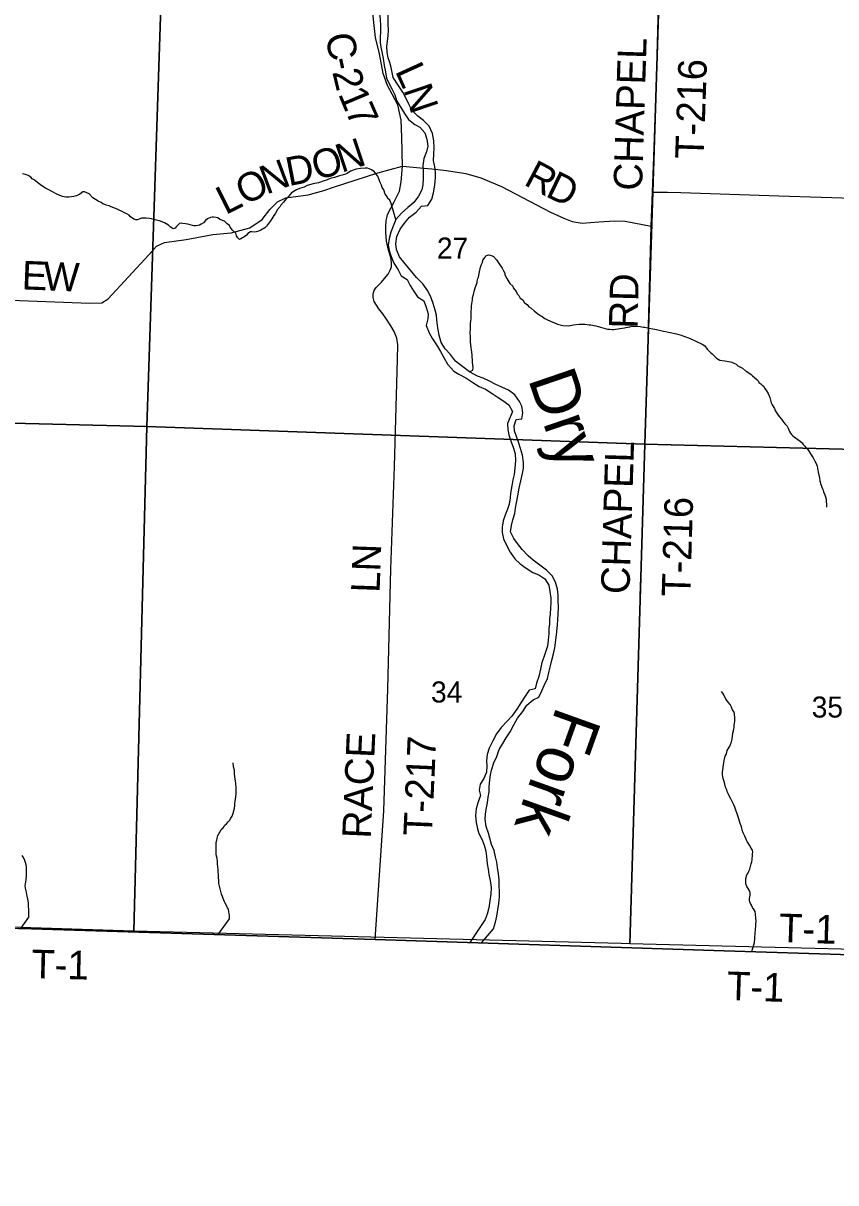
# Model space of a CAD drawing. Extents: x 1310247 to 1552180, y 377264 to 706493.
# Drawn here: x 1328257 to 1336785, y 480623 to 492789 of the extents above; entities that cross this region are included whole.
import ezdxf

# ---------------------------------------------------------------- set-up
doc = ezdxf.new("R2010")
doc.units = 0
for name, color, linetype in [('GM_X_Adjacent_County', 7, 'Continuous'), ('GM_X_County', 7, 'Continuous'), ('GM_X_County_Road', 7, 'Continuous'), ('GM_X_County_Road_Text', 7, 'Continuous'), ('GM_X_Minor_River', 7, 'Continuous'), ('GM_X_Minor_River_Text', 7, 'Continuous'), ('GM_X_Section', 7, 'Continuous'), ('GM_X_Section_Text', 7, 'Continuous'), ('GM_X_Township', 7, 'Continuous'), ('GM_X_Township_Road', 7, 'Continuous'), ('GM_X_Township_Road_Text', 7, 'Continuous'), ('GM_X_Township_ROW', 7, 'Continuous')]:
    doc.layers.add(name, color=color, linetype=linetype)

msp = doc.modelspace()

# ---------------------------------------------------------------- linework, layer by layer
at = {"layer": 'GM_X_Adjacent_County'}
msp.add_lwpolyline([(1311930, 473340), (1312230, 481623), (1312308, 483784), (1318929, 483579), (1321046, 483514), (1321136, 483511), (1321869, 483488), (1322123, 483480), (1323707, 483431), (1325989, 483347), (1327303, 483322), (1327412, 483318), (1328130, 483294), (1328206, 483291), (1328343, 483287), (1331950, 483175), (1335615, 483058), (1337392, 483001)], dxfattribs=at)
at = {"layer": 'GM_X_County'}
msp.add_lwpolyline([(1337392, 483001), (1335615, 483058), (1331950, 483175), (1328343, 483287), (1328206, 483291)], dxfattribs=at)
at = {"layer": 'GM_X_County_Road'}
for points in [[(1332238, 491289), (1332231, 491593), (1332223, 491770), (1332190, 491933), (1332130, 492044), (1332082, 492136), (1332035, 492261), (1331996, 492468), (1331955, 492638), (1331915, 492990), (1331892, 493143), (1331876, 493464), (1331840, 493608), (1331766, 493746), (1331651, 493921), (1331448, 494140), (1331228, 494295), (1330896, 494460), (1330638, 494558), (1330379, 494645), (1330272, 494712), (1330218, 494757), (1330196, 494814), (1330194, 494825)], [(1327573, 489903), (1328958, 489851), (1329081, 489855), (1329149, 489897), (1329574, 490360), (1329655, 490448), (1329739, 490487), (1329966, 490518), (1330247, 490572), (1330440, 490588), (1330634, 490643), (1330764, 490728), (1330847, 490836), (1330926, 490915), (1331013, 490955), (1331247, 490988), (1331412, 491034), (1331515, 491067), (1331979, 491219), (1332238, 491289)], [(1332238, 491289), (1332349, 491278), (1332424, 491271), (1332546, 491261), (1332699, 491245), (1332903, 491213), (1333059, 491167), (1333275, 491077), (1333792, 490808), (1333930, 490743), (1334020, 490708), (1334124, 490692), (1334297, 490704), (1334467, 490715), (1334574, 490712), (1334848, 490661), (1334863, 491017), (1335018, 491015)], [(1335018, 491015), (1335159, 491013), (1336186, 490979), (1337074, 490951), (1337926, 490924), (1338970, 490886), (1339596, 490862), (1340611, 490828), (1341219, 490803), (1341888, 490779), (1342113, 490773)]]:
    msp.add_lwpolyline(points, dxfattribs=at)
at = {"layer": 'GM_X_Minor_River'}
msp.add_line((1332943, 483144), (1333068, 483140), dxfattribs=at)
for points in [[(1331933, 493545), (1331942, 493468), (1331950, 493390), (1331950, 493338), (1331960, 493257), (1331970, 493198), (1331978, 493134), (1331983, 493055), (1331986, 493005), (1331990, 492954), (1331998, 492888), (1332004, 492827), (1332008, 492765), (1332006, 492697), (1332002, 492641), (1332004, 492586), (1332011, 492536), (1332025, 492471), (1332035, 492419), (1332047, 492346), (1332060, 492277), (1332070, 492210), (1332127, 492101)], [(1332140, 492219), (1332118, 492325), (1332104, 492376), (1332087, 492427), (1332077, 492482), (1332075, 492548), (1332079, 492600), (1332089, 492660), (1332091, 492714), (1332089, 492779), (1332086, 492831), (1332088, 492897)], [(1333790, 486048), (1333806, 486106), (1333824, 486174), (1333838, 486236), (1333843, 486288), (1333859, 486404), (1333865, 486476), (1333869, 486534), (1333872, 486590), (1333876, 486664), (1333872, 486735), (1333870, 486785), (1333864, 486850), (1333844, 486924), (1333808, 486992), (1333749, 487050), (1333678, 487104), (1333610, 487156), (1333555, 487202), (1333493, 487268), (1333444, 487330), (1333406, 487381), (1333372, 487454), (1333381, 487518), (1333395, 487578), (1333415, 487644), (1333425, 487700), (1333434, 487758), (1333447, 487832), (1333463, 487912), (1333481, 487987), (1333496, 488063), (1333509, 488121), (1333509, 488181), (1333497, 488258), (1333477, 488327), (1333459, 488382), (1333436, 488441), (1333414, 488513), (1333408, 488564), (1333430, 488632), (1333490, 488638), (1333502, 488702), (1333490, 488770), (1333467, 488821), (1333415, 488889), (1333350, 488939), (1333279, 488971), (1333216, 488999), (1333151, 489035), (1333083, 489065), (1333024, 489085), (1332941, 489130), (1332872, 489182), (1332795, 489243), (1332741, 489314), (1332687, 489372), (1332643, 489440), (1332621, 489517), (1332607, 489593), (1332599, 489676), (1332593, 489726), (1332580, 489777), (1332560, 489848), (1332538, 489909), (1332504, 489980), (1332450, 490056), (1332386, 490120), (1332320, 490198), (1332264, 490266), (1332207, 490338), (1332174, 490415), (1332167, 490474), (1332178, 490552), (1332214, 490629), (1332258, 490690), (1332312, 490753), (1332380, 490807), (1332438, 490869), (1332504, 490878), (1332544, 490943), (1332564, 491010), (1332574, 491068), (1332579, 491120), (1332585, 491176), (1332583, 491229), (1332578, 491281), (1332564, 491350), (1332566, 491414), (1332570, 491484), (1332566, 491554), (1332552, 491633), (1332516, 491708), (1332458, 491768), (1332397, 491814), (1332337, 491878), (1332301, 491946), (1332274, 492005), (1332242, 492066), (1332194, 492140), (1332140, 492219)], [(1332127, 492101), (1332157, 492038), (1332175, 491978), (1332260, 491843), (1332302, 491779), (1332366, 491727), (1332420, 491697), (1332472, 491637), (1332492, 491571), (1332502, 491500), (1332490, 491438), (1332460, 491369), (1332450, 491295), (1332454, 491232), (1332456, 491160), (1332452, 491094), (1332439, 491042), (1332405, 490973), (1332358, 490906), (1332295, 490854), (1332229, 490797), (1332167, 490731), (1332139, 490661), (1332115, 490596), (1332097, 490530), (1332089, 490460), (1332103, 490391), (1332119, 490341), (1332147, 490272), (1332191, 490202), (1332224, 490139), (1332285, 490099), (1332319, 490038), (1332352, 489980), (1332394, 489919), (1332463, 489875), (1332487, 489808), (1332507, 489739), (1332505, 489687), (1332487, 489619), (1332517, 489542), (1332553, 489477), (1332596, 489413), (1332638, 489344), (1332672, 489280), (1332710, 489211), (1332778, 489137), (1332830, 489107), (1332903, 489069), (1332976, 489020), (1333041, 488978), (1333110, 488950), (1333179, 488904), (1333230, 488868), (1333291, 488830), (1333354, 488784), (1333392, 488715), (1333368, 488655), (1333338, 488590), (1333342, 488524), (1333355, 488471), (1333379, 488396), (1333401, 488329), (1333419, 488270), (1333425, 488200), (1333417, 488120), (1333411, 488054), (1333397, 487998), (1333385, 487934), (1333371, 487860), (1333366, 487808), (1333356, 487744), (1333340, 487690), (1333319, 487639), (1333295, 487567), (1333285, 487503), (1333285, 487445), (1333299, 487378), (1333331, 487307), (1333369, 487238), (1333417, 487170), (1333474, 487118), (1333535, 487072), (1333604, 487026), (1333669, 487000), (1333732, 486960), (1333773, 486892), (1333783, 486826), (1333793, 486757), (1333795, 486705), (1333792, 486655), (1333786, 486589), (1333782, 486539), (1333781, 486488), (1333775, 486438), (1333772, 486386), (1333768, 486316), (1333758, 486254), (1333743, 486202), (1333721, 486137), (1333701, 486081)], [(1332167, 490731), (1332119, 490898), (1332104, 490931), (1332084, 490951), (1332081, 490965), (1332057, 490996), (1332041, 491039), (1332023, 491065), (1332016, 491088), (1332003, 491116), (1331993, 491144), (1331978, 491183), (1331963, 491206), (1331940, 491234), (1331904, 491255), (1331869, 491267), (1331847, 491269), (1331796, 491265), (1331750, 491258), (1331693, 491238), (1331656, 491213), (1331638, 491205), (1331606, 491194), (1331575, 491187), (1331545, 491178), (1331523, 491171), (1331478, 491158), (1331441, 491143), (1331415, 491134), (1331356, 491115), (1331300, 491105), (1331239, 491087), (1331205, 491070), (1331158, 491055), (1331127, 491040), (1331072, 491008), (1331037, 490967), (1331020, 490949), (1330989, 490910), (1330960, 490881), (1330954, 490867), (1330925, 490835), (1330901, 490788), (1330889, 490770), (1330868, 490735), (1330851, 490715), (1330841, 490700), (1330832, 490686), (1330809, 490660), (1330793, 490641), (1330750, 490616), (1330726, 490607), (1330703, 490601), (1330681, 490598), (1330655, 490601), (1330641, 490599), (1330616, 490582), (1330602, 490566), (1330573, 490545), (1330559, 490538), (1330541, 490526), (1330526, 490520), (1330509, 490537), (1330495, 490558), (1330490, 490586), (1330453, 490619), (1330430, 490650), (1330422, 490666), (1330397, 490685), (1330385, 490699), (1330369, 490712), (1330322, 490731), (1330300, 490746), (1330284, 490750), (1330256, 490753), (1330242, 490754), (1330222, 490750), (1330193, 490737), (1330171, 490718), (1330148, 490696), (1330126, 490679), (1330107, 490669), (1330071, 490664), (1330049, 490663), (1330033, 490668), (1329985, 490679), (1329959, 490684), (1329929, 490689), (1329915, 490691), (1329897, 490688), (1329882, 490672), (1329862, 490653), (1329851, 490639), (1329831, 490632), (1329800, 490651), (1329782, 490669), (1329741, 490694), (1329715, 490705), (1329687, 490714), (1329669, 490719), (1329629, 490730)], [(1329629, 490730), (1329603, 490737), (1329583, 490739), (1329547, 490744), (1329529, 490743), (1329513, 490743), (1329499, 490742), (1329473, 490733), (1329457, 490727), (1329439, 490726), (1329419, 490734), (1329383, 490759), (1329368, 490774), (1329346, 490790), (1329320, 490801), (1329297, 490812), (1329271, 490825), (1329251, 490835), (1329231, 490844), (1329217, 490849), (1329174, 490866), (1329158, 490872), (1329128, 490881), (1329114, 490888), (1329094, 490892), (1329076, 490907), (1329045, 490920), (1328988, 490956), (1328951, 490997), (1328901, 491018), (1328883, 491019), (1328852, 490996), (1328832, 490984), (1328816, 490979), (1328801, 490973), (1328787, 490972), (1328763, 490968), (1328737, 490965), (1328717, 490964), (1328703, 490962), (1328671, 490969), (1328641, 490980), (1328605, 490997), (1328566, 491018), (1328532, 491036), (1328513, 491046), (1328491, 491059), (1328465, 491076), (1328438, 491094), (1328410, 491115), (1328385, 491136), (1328367, 491149), (1328353, 491157), (1328336, 491172), (1328308, 491191), (1328292, 491199), (1328266, 491206), (1328250, 491208)], [(1332941, 489130), (1332977, 489149), (1332978, 489175), (1332974, 489228), (1332972, 489254), (1332969, 489292), (1332970, 489310), (1332961, 489362), (1332960, 489382), (1332952, 489445), (1332951, 489473), (1332951, 489495), (1332949, 489543), (1332950, 489583), (1332953, 489619), (1332953, 489635), (1332956, 489667), (1332957, 489687), (1332960, 489736), (1332963, 489826), (1332965, 489844), (1332971, 489886), (1332971, 489906), (1332982, 489943), (1332987, 489959), (1332989, 489973), (1333000, 490011), (1333007, 490031), (1333020, 490067), (1333022, 490081), (1333029, 490111), (1333034, 490126), (1333043, 490162), (1333047, 490182), (1333057, 490230), (1333065, 490250), (1333078, 490278), (1333081, 490302), (1333106, 490335), (1333114, 490349), (1333139, 490358), (1333157, 490355), (1333177, 490349), (1333192, 490342), (1333224, 490307), (1333252, 490264), (1333285, 490219), (1333298, 490191), (1333310, 490168), (1333313, 490150), (1333334, 490109), (1333365, 490058), (1333394, 490029), (1333398, 490011), (1333429, 489974), (1333440, 489950), (1333460, 489933), (1333473, 489905), (1333500, 489886), (1333518, 489855), (1333547, 489838), (1333563, 489814), (1333588, 489799), (1333619, 489770), (1333659, 489741), (1333690, 489718), (1333704, 489711), (1333732, 489690), (1333747, 489684), (1333799, 489660), (1333845, 489641), (1333864, 489632), (1333922, 489616), (1333976, 489615), (1334017, 489620), (1334033, 489623), (1334093, 489631), (1334155, 489632), (1334195, 489626), (1334213, 489624), (1334267, 489614), (1334291, 489607), (1334389, 489580), (1334411, 489580), (1334433, 489577), (1334455, 489576), (1334473, 489580), (1334501, 489583), (1334517, 489587), (1334566, 489593), (1334582, 489597), (1334624, 489605), (1334648, 489609), (1334668, 489608), (1334683, 489610), (1334731, 489606), (1334767, 489601), (1334781, 489599), (1334827, 489591), (1334866, 489582), (1334886, 489578)], [(1334886, 489578), (1334936, 489568), (1334976, 489559), (1334996, 489556), (1335030, 489547), (1335048, 489543), (1335112, 489531), (1335161, 489515), (1335179, 489509), (1335239, 489489), (1335263, 489478), (1335310, 489455), (1335330, 489446), (1335370, 489427), (1335384, 489420), (1335409, 489405), (1335436, 489368), (1335450, 489354), (1335473, 489331), (1335489, 489321), (1335520, 489288), (1335532, 489273), (1335552, 489263), (1335569, 489254), (1335619, 489247), (1335643, 489244), (1335659, 489241), (1335679, 489235), (1335693, 489232), (1335707, 489224), (1335739, 489211), (1335758, 489194), (1335806, 489171), (1335839, 489142), (1335853, 489133), (1335896, 489102), (1335910, 489088), (1335955, 489050), (1335969, 489036), (1335976, 489021), (1335998, 489007), (1336013, 488992), (1336027, 488980), (1336041, 488957), (1336058, 488933), (1336075, 488904), (1336092, 488861), (1336096, 488847), (1336103, 488821), (1336108, 488807), (1336118, 488784), (1336143, 488748), (1336150, 488725), (1336158, 488707), (1336173, 488686), (1336189, 488664), (1336216, 488635), (1336229, 488613), (1336249, 488586), (1336274, 488561), (1336285, 488539), (1336293, 488524), (1336300, 488504), (1336310, 488488), (1336320, 488473), (1336335, 488461), (1336361, 488438), (1336412, 488403), (1336431, 488386), (1336443, 488369), (1336459, 488351), (1336472, 488337), (1336488, 488322), (1336499, 488306), (1336509, 488287), (1336526, 488261), (1336547, 488230), (1336564, 488193), (1336582, 488163), (1336589, 488142), (1336594, 488120), (1336598, 488098), (1336601, 488078), (1336610, 488032), (1336614, 488017), (1336619, 487989), (1336628, 487949), (1336646, 487904), (1336652, 487890), (1336656, 487874), (1336671, 487841), (1336678, 487819), (1336683, 487795), (1336685, 487779), (1336685, 487764), (1336686, 487748), (1336686, 487728), (1336689, 487710)], [(1333701, 486081), (1333687, 486013), (1333667, 485936), (1333645, 485866), (1333631, 485806), (1333568, 485790), (1333524, 485727), (1333480, 485658), (1333438, 485591), (1333384, 485518), (1333336, 485467), (1333272, 485401), (1333224, 485334), (1333186, 485259), (1333149, 485184), (1333125, 485116), (1333119, 485050), (1333122, 484998), (1333118, 484931), (1333090, 484866), (1333054, 484805), (1333044, 484741), (1333055, 484688), (1333030, 484609), (1333012, 484545), (1333004, 484475), (1333010, 484404), (1333024, 484338), (1333039, 484287), (1333075, 484220), (1333096, 484167), (1333114, 484102), (1333120, 484046), (1333128, 483969), (1333137, 483915), (1333145, 483858), (1333157, 483794), (1333167, 483723), (1333163, 483651), (1333155, 483583), (1333143, 483509), (1333127, 483441), (1333105, 483385), (1332943, 483144)], [(1333068, 483140), (1333194, 483286), (1333215, 483356), (1333229, 483422), (1333238, 483486), (1333250, 483552), (1333256, 483622), (1333254, 483682), (1333252, 483733), (1333252, 483801), (1333245, 483865), (1333235, 483930), (1333227, 483988), (1333214, 484043), (1333198, 484110), (1333172, 484173), (1333154, 484238), (1333139, 484290), (1333117, 484361), (1333106, 484438), (1333109, 484490), (1333115, 484540), (1333131, 484608), (1333138, 484670), (1333146, 484724), (1333147, 484776), (1333154, 484850), (1333161, 484902), (1333171, 484954), (1333195, 485028), (1333227, 485097), (1333253, 485168), (1333289, 485232), (1333327, 485293), (1333367, 485356), (1333405, 485429), (1333445, 485498), (1333501, 485569), (1333543, 485634), (1333609, 485690), (1333668, 485719), (1333700, 485784), (1333726, 485841), (1333760, 485915), (1333777, 485991), (1333790, 486048)], [(1335659, 485661), (1335630, 485696), (1335611, 485742), (1335601, 485759), (1335586, 485777)], [(1335902, 483050), (1335930, 483145), (1335935, 483183), (1335936, 483209), (1335938, 483223), (1335939, 483243), (1335942, 483277), (1335945, 483321), (1335947, 483337), (1335948, 483367), (1335947, 483401), (1335942, 483443), (1335937, 483470), (1335928, 483486), (1335912, 483511), (1335901, 483535), (1335889, 483553), (1335884, 483572), (1335880, 483590), (1335879, 483606), (1335883, 483624), (1335886, 483642), (1335885, 483668), (1335877, 483694), (1335864, 483711), (1335852, 483733), (1335841, 483761), (1335841, 483814), (1335852, 483853), (1335860, 483869), (1335873, 483893), (1335882, 483915), (1335891, 483943), (1335897, 483970), (1335904, 483992), (1335907, 484012), (1335907, 484028), (1335910, 484050), (1335912, 484076), (1335913, 484092), (1335910, 484114), (1335898, 484133), (1335879, 484166), (1335869, 484184), (1335856, 484204), (1335848, 484219), (1335841, 484237), (1335829, 484259), (1335812, 484296), (1335803, 484324), (1335798, 484345), (1335792, 484367), (1335783, 484391), (1335776, 484417), (1335768, 484442), (1335761, 484464), (1335754, 484484), (1335746, 484505), (1335741, 484523), (1335733, 484543), (1335724, 484563), (1335714, 484590), (1335703, 484610), (1335684, 484651), (1335671, 484675), (1335654, 484708), (1335646, 484728), (1335641, 484746), (1335629, 484775), (1335620, 484805), (1335617, 484823), (1335604, 484866), (1335597, 484904), (1335596, 484932), (1335603, 484980), (1335606, 485010), (1335611, 485026), (1335615, 485052), (1335622, 485084), (1335625, 485098), (1335633, 485118), (1335640, 485140), (1335644, 485158), (1335663, 485187), (1335672, 485203), (1335680, 485221), (1335689, 485249), (1335696, 485276), (1335706, 485340), (1335713, 485364), (1335715, 485382), (1335718, 485402), (1335718, 485422), (1335724, 485468), (1335725, 485506), (1335722, 485536), (1335718, 485561), (1335701, 485585), (1335688, 485620), (1335678, 485642), (1335659, 485661)], [(1330304, 483227), (1330422, 483392), (1330421, 483416), (1330421, 483430), (1330419, 483444), (1330416, 483466), (1330411, 483495), (1330403, 483509), (1330392, 483531), (1330378, 483556), (1330371, 483570), (1330363, 483590), (1330356, 483607), (1330348, 483627), (1330339, 483651), (1330330, 483680), (1330323, 483706), (1330317, 483736), (1330312, 483764), (1330309, 483793), (1330308, 483825), (1330307, 483855), (1330304, 483885), (1330302, 483909), (1330301, 483937), (1330298, 483970), (1330295, 483998), (1330292, 484024), (1330286, 484050), (1330283, 484074), (1330282, 484100), (1330283, 484130), (1330282, 484165), (1330284, 484195), (1330289, 484217), (1330292, 484239), (1330298, 484252), (1330301, 484268), (1330313, 484292), (1330326, 484306), (1330336, 484331), (1330355, 484347), (1330367, 484363), (1330372, 484377), (1330390, 484388), (1330407, 484410), (1330423, 484425), (1330438, 484447), (1330451, 484470), (1330462, 484502), (1330473, 484552), (1330478, 484578), (1330479, 484602), (1330481, 484624), (1330489, 484674), (1330492, 484704), (1330493, 484736), (1330492, 484772), (1330487, 484812), (1330480, 484861), (1330474, 484911), (1330473, 484953), (1330464, 484988), (1330461, 485028)], [(1328234, 483291), (1328317, 483411), (1328316, 483443), (1328317, 483493), (1328314, 483521), (1328313, 483554), (1328308, 483586), (1328301, 483618), (1328296, 483646), (1328291, 483673), (1328282, 483713), (1328278, 483741), (1328281, 483755), (1328286, 483785), (1328288, 483799), (1328289, 483813), (1328291, 483835), (1328292, 483875), (1328291, 483897), (1328293, 483911), (1328292, 483933), (1328289, 483959), (1328283, 483982), (1328274, 484006), (1328261, 484035), (1328247, 484057)]]:
    msp.add_lwpolyline(points, dxfattribs=at)
at = {"layer": 'GM_X_Section'}
for points in [[(1324514, 493943), (1329731, 493803), (1329553, 488557), (1324323, 488687)], [(1329731, 493803), (1334950, 493664), (1334782, 488372), (1329553, 488557)], [(1340179, 493497), (1340031, 488240), (1334782, 488372), (1334950, 493664)], [(1324323, 488687), (1329553, 488557), (1329417, 483264), (1328122, 483306), (1324202, 483425)], [(1329553, 488557), (1334782, 488372), (1334625, 483131), (1334531, 483133), (1329417, 483264)], [(1340031, 488240), (1339866, 482985), (1338783, 483025), (1334625, 483131), (1334782, 488372)]]:
    msp.add_lwpolyline(points, close=True, dxfattribs=at)
at = {"layer": 'GM_X_Township'}
msp.add_lwpolyline([(1337392, 483001), (1335615, 483058), (1331950, 483175), (1328343, 483287), (1328206, 483291)], dxfattribs=at)
at = {"layer": 'GM_X_Township_Road'}
for points in [[(1334863, 491017), (1334875, 491388), (1334904, 492203), (1334933, 493217), (1334951, 493700), (1334975, 494923)], [(1331950, 483175), (1332041, 484526), (1332085, 485806), (1332117, 487060), (1332155, 488137), (1332187, 489260), (1332189, 489415), (1332177, 489483), (1332151, 489554), (1332116, 489615), (1332069, 489683), (1332031, 489740), (1331991, 489792), (1331942, 489870), (1331930, 489910), (1331929, 489950), (1331942, 489986), (1331963, 490016), (1332017, 490072), (1332049, 490109), (1332088, 490156), (1332108, 490198), (1332121, 490234), (1332121, 490279), (1332115, 490330), (1332092, 490407), (1332070, 490503), (1332063, 490594), (1332063, 490653), (1332068, 490719), (1332076, 490760), (1332082, 490783), (1332150, 490913), (1332207, 491026), (1332224, 491124), (1332238, 491289)], [(1334731, 486778), (1334747, 487172), (1334786, 488370), (1334811, 489353), (1334848, 490661)], [(1328343, 483287), (1331950, 483175)], [(1335651, 483057), (1337392, 483001)]]:
    msp.add_lwpolyline(points, dxfattribs=at)
at = {"layer": 'GM_X_Township_ROW'}
msp.add_lwpolyline([(1331950, 483175), (1335615, 483058), (1335651, 483057)], dxfattribs=at)

# ---------------------------------------------------------------- texts
at = {"layer": 'GM_X_County_Road_Text'}
for s, rotation, p in [('C', 279.3224, (1331430, 492665)), ('-', 281.9157, (1331472, 492407)), ('L', 294.3767, (1332156, 492289)), ('2', 283.4245, (1331500, 492278)), ('1', 292.7278, (1331559, 492048)), ('N', 288.6704, (1332245, 492092)), ('7', 293.7124, (1331633, 491872)), ('N', 18.3722, (1331598, 491217)), ('D', 10.8676, (1331044, 491079)), ('O', 17.0653, (1331338, 491137)), ('N', 20.6487, (1330810, 490989)), ('R', 332.0967, (1333499, 491099)), ('O', 26.4852, (1330582, 490875)), ('D', 334.1867, (1333727, 490978)), ('L', 26.5653, (1330381, 490775)), ('E', 357.7087, (1328238, 489997)), ('W', 357.7227, (1328463, 489988))]:
    msp.add_text(s, height=300, rotation=rotation, dxfattribs=at).set_placement(p)
at = {"layer": 'GM_X_Minor_River_Text'}
for s, height, rotation, p in [('Dry', 500.1, 288.9139, (1333552, 489058)), ('Fork', 500, 250.3083, (1333860, 485635))]:
    msp.add_text(s, height=height, rotation=rotation, dxfattribs=at).set_placement(p)
at = {"layer": 'GM_X_Section_Text'}
for s, p in [('27', (1332599, 490319)), ('34', (1332537, 485662)), ('35', (1336532, 485504))]:
    msp.add_text(s, height=221, rotation=0, dxfattribs=at).set_placement(p)
at = {"layer": 'GM_X_Township_Road_Text'}
for s, rotation, p in [('CHAPEL', 88.2376, (1334751, 491029)), ('T-216', 88.0459, (1335398, 491361)), ('RD', 88.5187, (1334703, 489581)), ('CHAPEL', 88.2321, (1334619, 486796)), ('T-216', 88.3153, (1335257, 486768)), ('LN', 87.9361, (1331997, 486810)), ('RACE', 87.4672, (1331904, 484231)), ('T-217', 87.4725, (1332546, 484257)), ('T-1', 358.1715, (1336186, 483149)), ('T-1', 358.5678, (1328340, 482770)), ('T-1', 358.091, (1335639, 482541))]:
    msp.add_text(s, height=300, rotation=rotation, dxfattribs=at).set_placement(p)

doc.saveas('drawing.dxf')
